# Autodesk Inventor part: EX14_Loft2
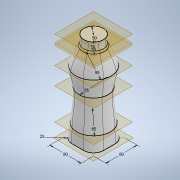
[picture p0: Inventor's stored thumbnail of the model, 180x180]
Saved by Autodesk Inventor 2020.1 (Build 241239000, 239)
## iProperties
Created: 2019-10
Part Number: EX14_Loft2
Material: Generic
Document SubType Name: Modeling
Designer: Synergysoft Dell02
Density: 1 g/cm^3
Appearance: Default
Author: Synergysoft Dell02
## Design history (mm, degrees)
sketch "Sketch1"
  geometry: L1 (15, -40)-(-15, -40); L2 (-40, -15)-(-40, 15); L3 (-15, 40)-(15, 40); L4 (40, 15)-(40, -15); L5 (40, -40)-(-40, 40); L6 (-40, -40)-(40, 40); A1 r 25 centre (15, 15) between (40, 15) and (15, 40); A2 r 25 centre (15, -15) between (15, -40) and (40, -15); A3 r 25 centre (-15, -15) between (-40, -15) and (-15, -40); A4 r 25 centre (-15, 15) between (-15, 40) and (-40, 15); 1 further point
  constraints: 12 end point, 8 point on circle, 8 point on line, 8 tangent, 4 centre point, 3 equal radius, 2 midpoint, 2 parallel, 1 horizontal, 1 perpendicular
  dimensions: "d0" = 80 distance of L5.end L6.end; "d1" = 80 distance of L6.start L5.end; "d2" = 25 radius of A1
workplane "Work Plane1"
sketch "Sketch2"
  geometry: C1 r 42.5 at (0, 0); 1 further point
  constraints: 1 centre point, 1 coincident
  dimensions: "d4" = 85 diameter of C1
workplane "Work Plane2"
sketch "Sketch3"
  geometry: C1 r 37.5 at (0, 0); 1 further point
  constraints: 1 centre point, 1 coincident
  dimensions: "d6" = 75 diameter of C1
workplane "Work Plane3"
sketch "Sketch4"
  geometry: C1 r 45 at (0, 0); 1 further point
  constraints: 1 centre point, 1 coincident
  dimensions: "d8" = 90 diameter of C1
workplane "Work Plane4"
sketch "Sketch5"
  geometry: C1 r 27.5 at (0, 0); 1 further point
  constraints: 1 centre point, 1 coincident
  dimensions: "d10" = 55 diameter of C1
workplane "Work Plane5"
sketch "Sketch6"
  geometry: C1 r 25 at (0, 0); 1 further point
  constraints: 1 centre point, 1 coincident
  dimensions: "d12" = 50 diameter of C1
workplane "Work Plane6"
sketch "Sketch7"
  geometry: C1 r 25 at (0, 0); 1 further point
  constraints: 1 centre point, 1 coincident
  dimensions: "d14" = 50 diameter of C1
loft "Loft1" dims "d15" = 0, "d16" = 90 deg, "d17" = 0, "d18" = 90 deg, "d19" = 0, "d20" = 90 deg, "d21" = 0, "d22" = 90 deg, "d23" = 0, "d24" = 90 deg, "d25" = 0, "d26" = 90 deg, "d27" = 0, "d28" = 90 deg
sketch "Sketch8"
  geometry: L1 (0, 0)-(0, 250)
  constraints: 2 end point, 1 vertical
  dimensions: "d29" = 250 distance of L1.start L1.end
loft "Loft2" sketch "Sketch8" dims "d30" = 0, "d31" = 90 deg, "d32" = 0, "d33" = 90 deg, "d34" = 0, "d35" = 90 deg, "d36" = 0, "d37" = 90 deg, "d38" = 0, "d39" = 90 deg, "d40" = 0, "d41" = 90 deg, "d42" = 0, "d43" = 90 deg, "d44" = 0, "d45" = 90 deg
body "Solid1"
other parameters: "d3" = 35, "d7" = 45, "d9" = 45, "d11" = 5
